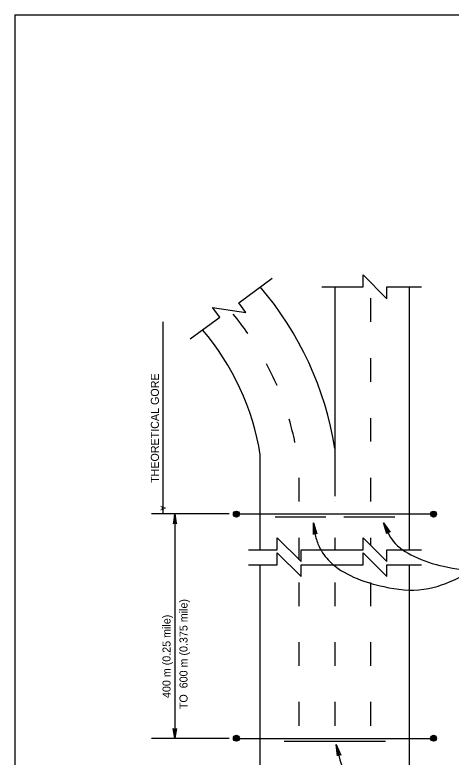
# Model space of a CAD drawing. Extents: x 640994 to 644422, y 298458 to 299646.
# Drawn here: x 641875.3 to 642038.9, y 298758.5 to 299036.6 of the extents above; entities that cross this region are included whole.
import ezdxf

# ---------------------------------------------------------------- set-up
doc = ezdxf.new("R2010")
doc.units = 0
doc.layers.add('1', color=7, linetype='Continuous')
doc.layers.add('2', color=7, linetype='Continuous')

msp = doc.modelspace()

# ---------------------------------------------------------------- linework, layer by layer
at = {"layer": '1'}
for q in [(642661.31, 299036.63), (641875.31, 298472.63)]:
    msp.add_line((641875.31, 299036.63), q, dxfattribs=at)
at = {"layer": '2'}
for p, q in [((641959.31, 298928.75), (641971.81, 298938)), ((641990.44, 298934.75), (642005.94, 298934.75)), ((641995.44, 298856.25), (641995.44, 298934.75)), ((642014.81, 298934.75), (642027.81, 298934.75)), ((642023.31, 298836.13), (642023.31, 298934.75)), ((641995.44, 298930.5), (641995.44, 298930.5)), ((642008.81, 298921.63), (642008.81, 298930.5)), ((641941.06, 298915.25), (641952.19, 298923.38)), ((641957.19, 298924.38), (641957.19, 298924.38)), ((641930.81, 298921.63), (641930.81, 298849.63)), ((641995.44, 298921.63), (641995.44, 298921.63)), ((641962.69, 298917.25), (641962.69, 298917.25)), ((641995.44, 298908), (641995.44, 298908)), ((642008.81, 298899.13), (642008.81, 298908)), ((641969.69, 298905.88), (641969.69, 298905.88)), ((641995.44, 298899.13), (641995.44, 298899.13)), ((641973.56, 298897.75), (641973.56, 298897.75)), ((641978.19, 298885.25), (641978.19, 298885.25)), ((641978.19, 298885.13), (641978.19, 298885.13)), ((641995.44, 298885.5), (641995.44, 298885.5)), ((642008.81, 298876.75), (642008.81, 298885.5)), ((641980.31, 298876.38), (641980.31, 298876.38)), ((641995.44, 298876.75), (641995.44, 298876.75)), ((641967.31, 298836.13), (641967.31, 298871.75)), ((641981.94, 298854.25), (641981.94, 298863.13)), ((641995.44, 298863.13), (641995.44, 298863.13)), ((642008.81, 298854.25), (642008.81, 298863.13)), ((641995.44, 298854.25), (641995.44, 298854.25)), ((641955.69, 298849.63), (641926.56, 298849.63)), ((641935.31, 298849.63), (641935.31, 298765.5)), ((641959.19, 298849.75), (641957.44, 298849.38)), ((641958.19, 298848.63), (641957.44, 298849.75)), ((641957.44, 298849.75), (641958.81, 298848.63)), ((641957.44, 298849.38), (641959.31, 298849.5)), ((641958.81, 298850.25), (641957.56, 298849.88)), ((641957.56, 298849.88), (641959.19, 298849.75)), ((641959.31, 298849.5), (641957.69, 298849)), ((641957.69, 298849), (641959.19, 298849)), ((641957.81, 298850.25), (641958.81, 298850.25)), ((641958.81, 298848.63), (641958.19, 298850.5)), ((641958.19, 298850.5), (641959.31, 298849.25)), ((641959.19, 298849), (641958.19, 298848.63)), ((641958.44, 298849.63), (642032.31, 298849.63)), ((641958.44, 298849.63), (641958.44, 298849.63)), ((641959.31, 298849.25), (641959.06, 298850.38)), ((641972.94, 298848.5), (641991.94, 298848.5)), ((641998.69, 298848.5), (642017.81, 298848.5)), ((642032.94, 298849.75), (642031.31, 298849.38)), ((642032.19, 298848.63), (642031.31, 298849.75)), ((642031.31, 298849.75), (642032.81, 298848.63)), ((642031.31, 298849.38), (642033.19, 298849.5)), ((642032.69, 298850.25), (642031.44, 298849.88)), ((642031.44, 298849.88), (642032.94, 298849.75)), ((642033.19, 298849.5), (642031.56, 298849)), ((642031.56, 298849), (642033.06, 298849)), ((642031.69, 298850.25), (642032.69, 298850.25)), ((642032.81, 298848.63), (642032.19, 298850.5)), ((642032.19, 298850.5), (642033.19, 298849.25)), ((642033.06, 298849), (642032.19, 298848.63)), ((642032.31, 298849.63), (642032.31, 298849.63)), ((642033.19, 298849.25), (642032.94, 298850.38)), ((641981.94, 298832.38), (641981.94, 298840.63)), ((641995.44, 298840.75), (641995.44, 298840.75)), ((641995.44, 298840.75), (641995.44, 298840.75)), ((641995.44, 298840.63), (641995.44, 298840.63)), ((641995.44, 298840.63), (641995.44, 298840.63)), ((641995.44, 298836.13), (641995.44, 298840.63)), ((642008.81, 298837.75), (642008.81, 298840.63)), ((641962.94, 298836.13), (641973.69, 298836.13)), ((641982.69, 298836.13), (642005.94, 298836.13)), ((642014.81, 298836.13), (642027.81, 298836.13)), ((641962.94, 298830.5), (641973.69, 298830.5)), ((641967.31, 298752.13), (641967.31, 298830.5)), ((641982.69, 298830.5), (642005.94, 298830.5)), ((642014.81, 298830.5), (642027.81, 298830.5)), ((642023.31, 298752.13), (642023.31, 298830.5)), ((641981.94, 298815.13), (641981.94, 298824)), ((641995.44, 298824), (641995.44, 298824)), ((641995.44, 298815.13), (641995.44, 298824)), ((642008.81, 298815.13), (642008.81, 298824)), ((641995.44, 298815.13), (641995.44, 298815.13)), ((641981.94, 298792.75), (641981.94, 298801.63)), ((641995.44, 298801.63), (641995.44, 298801.63)), ((641995.44, 298792.75), (641995.44, 298801.63)), ((642008.81, 298792.75), (642008.81, 298801.63)), ((641995.44, 298792.75), (641995.44, 298792.75)), ((641981.94, 298770.25), (641981.94, 298779.25)), ((641995.44, 298779.25), (641995.44, 298779.25)), ((641995.44, 298770.25), (641995.44, 298779.25)), ((642008.81, 298770.25), (642008.81, 298779.25)), ((641995.44, 298770.38), (641995.44, 298770.38)), ((641995.44, 298770.25), (641995.44, 298770.25)), ((641955.69, 298765.5), (641926.56, 298765.5)), ((641959.19, 298765.75), (641957.44, 298765.5)), ((641958.19, 298764.75), (641957.44, 298765.63)), ((641957.44, 298765.63), (641958.81, 298764.75)), ((641957.44, 298765.5), (641959.31, 298765.5)), ((641958.81, 298766.25), (641957.56, 298765.88)), ((641957.56, 298765.88), (641959.19, 298765.75)), ((641959.31, 298765.5), (641957.69, 298765)), ((641957.69, 298765), (641959.19, 298765)), ((641957.81, 298766.25), (641958.81, 298766.25)), ((641958.81, 298764.75), (641958.19, 298766.5)), ((641958.19, 298766.5), (641959.31, 298765.38)), ((641959.19, 298765), (641958.19, 298764.75)), ((641958.44, 298765.5), (642032.31, 298765.5)), ((641958.44, 298765.5), (641958.44, 298765.5)), ((641959.31, 298765.38), (641959.06, 298766.38)), ((642032.94, 298765.75), (642031.31, 298765.5)), ((642032.19, 298764.75), (642031.31, 298765.63)), ((642031.31, 298765.63), (642032.81, 298764.75)), ((642031.31, 298765.5), (642033.19, 298765.5)), ((642032.69, 298766.25), (642031.44, 298765.88)), ((642031.44, 298765.88), (642032.94, 298765.75)), ((642033.19, 298765.5), (642031.56, 298765)), ((642031.56, 298765), (642033.06, 298765)), ((642031.69, 298766.25), (642032.69, 298766.25)), ((642032.81, 298764.75), (642032.19, 298766.5)), ((642032.19, 298766.5), (642033.19, 298765.38)), ((642033.06, 298765), (642032.19, 298764.75)), ((642032.31, 298765.5), (642032.31, 298765.5)), ((642033.19, 298765.38), (642032.94, 298766.38)), ((641976.31, 298764.5), (642014.31, 298764.5))]:
    msp.add_line(p, q, dxfattribs=at)
for points in [[(642005.94, 298934.75), (642005.94, 298939.25), (642014.81, 298930.25), (642014.81, 298934.75)], [(641952.19, 298923.38), (641949.44, 298927), (641961.94, 298925.13), (641959.31, 298928.75)], [(641935.81, 298846.13), (641935.56, 298846.25), (641935.31, 298849.63), (641935.81, 298846.13), (641935.94, 298845.88), (641935.31, 298849.63), (641935.19, 298846.25), (641934.94, 298846.13), (641935.31, 298849.63), (641934.69, 298845.88), (641934.94, 298846.13)], [(641987.44, 298842.13), (641987.69, 298842.38), (641987.31, 298846.25), (641987.44, 298842.13), (641987.31, 298841.88), (641987.31, 298846.25), (641988.06, 298842.38), (641988.44, 298842.38), (641987.31, 298846.25), (641988.56, 298842.13), (641988.44, 298842.38)], [(642014.94, 298842.38), (642015.19, 298842.63), (642013.56, 298846.25), (642014.94, 298842.38), (642014.81, 298842.13), (642013.56, 298846.25), (642015.44, 298842.88), (642015.81, 298842.88), (642013.56, 298846.25), (642016.06, 298842.75), (642015.81, 298842.88)], [(641973.69, 298836.13), (641973.69, 298840.63), (641982.69, 298831.75), (641982.69, 298836.13)], [(642005.94, 298836.13), (642005.94, 298840.63), (642014.81, 298831.75), (642014.81, 298836.13)], [(641973.69, 298830.5), (641973.69, 298835), (641982.69, 298826.13), (641982.69, 298830.5)], [(642005.94, 298830.5), (642005.94, 298835), (642014.81, 298826.13), (642014.81, 298830.5)], [(641935.81, 298769), (641935.56, 298768.88), (641935.31, 298765.5), (641935.81, 298769), (641935.94, 298769.25), (641935.31, 298765.5), (641935.19, 298768.88), (641934.94, 298769), (641935.31, 298765.5), (641934.69, 298769.25), (641934.94, 298769)], [(641996.35, 298759.23), (641996.73, 298759.47), (641995.83, 298763.29), (641996.35, 298759.23), (641996.24, 298759), (641995.83, 298763.29), (641997.01, 298759.48), (641997.4, 298759.44), (641995.83, 298763.29), (641997.58, 298759.23), (641997.4, 298759.44)]]:
    msp.add_lwpolyline(points, dxfattribs=at)
for centre in [(641958.39, 298849.57), (642032.29, 298849.57), (641958.39, 298765.59), (642032.29, 298765.59)]:
    msp.add_circle(centre, 1.12, dxfattribs=at)
for centre, radius, start, end in [((641872.79, 298854.18), 124.18, 9.2799, 40.4049), ((641872.79, 298854.18), 109.82, 35.0465, 39.7821), ((641872.42, 298856.28), 96.19, 9.2799, 40.4049), ((641872.79, 298854.18), 109.82, 23.362, 28.0977), ((641872.79, 298854.18), 109.82, 11.6775, 16.3438)]:
    msp.add_arc(centre, radius, start, end, dxfattribs=at)
for points in [[(641987.31, 298846.25), (641987.94, 298841.75), (641989.44, 298837.38), (641993.44, 298831.75), (642002.31, 298826), (642013.69, 298822.38), (642028.69, 298821.38), (642041.69, 298825.75), (642049.69, 298831.13), (642056.69, 298840.88), (642059.69, 298846.25)], [(642013.56, 298846.25), (642017.19, 298839.38), (642024.94, 298833.75), (642036.06, 298830), (642049.44, 298828), (642069.19, 298826.63), (642089.94, 298828), (642101.44, 298832.88), (642109.81, 298837.25), (642116.44, 298847.38)], [(641995.94, 298762.88), (641998.23, 298754.26), (642010.49, 298739.55), (642027.72, 298740.15), (642041.21, 298747.03), (642053.43, 298756.45), (642063.69, 298765.5)]]:
    msp.add_spline(points, degree=3, dxfattribs=at)

# ---------------------------------------------------------------- texts
for s, height, rotation, p in [('THEORETICAL GORE', 3, 90, (641929.31, 298861.25)), ('A', 2.09, 270, (641929.81, 298852.75)), ('TO  600 m (0.375 mile)', 3, 90, (641940.05, 298776.5)), ('  400 m (0.25 mile) ', 3, 90, (641933.68, 298778.43))]:
    msp.add_text(s, height=height, rotation=rotation, dxfattribs=at).set_placement(p)

doc.saveas('drawing.dxf')
